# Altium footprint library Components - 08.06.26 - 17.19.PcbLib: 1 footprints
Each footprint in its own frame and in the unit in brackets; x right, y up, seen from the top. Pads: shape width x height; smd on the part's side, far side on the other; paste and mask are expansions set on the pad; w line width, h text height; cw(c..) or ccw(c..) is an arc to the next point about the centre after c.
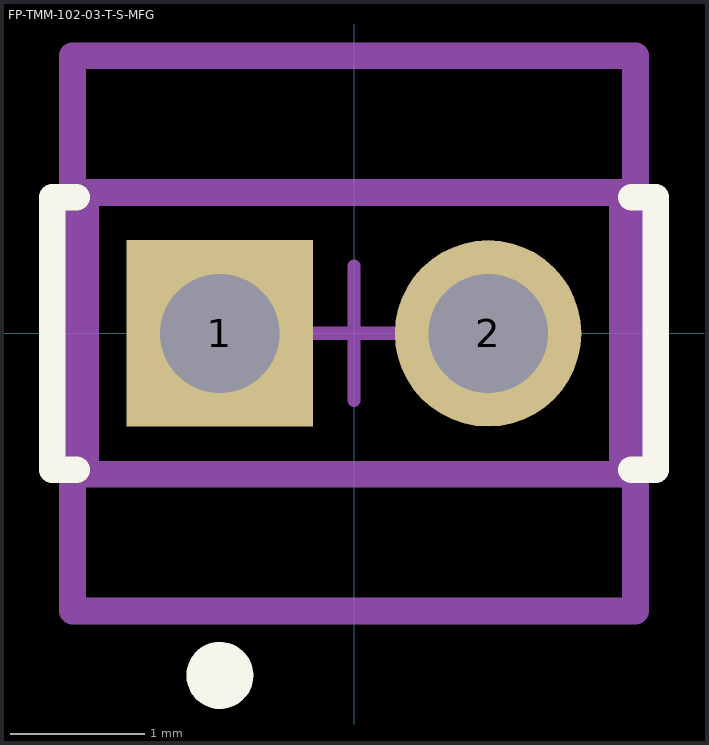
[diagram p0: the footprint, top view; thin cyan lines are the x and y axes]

## FP-TMM-102-03-T-S-MFG [mm]
pads (2):
  rect 1.39x1.39 hole 0.89 paste-2539.97 mask+0: 1(-1,0)
  round 1.39 hole 0.89 paste-2539.97 mask+0: 2(1,0)
Top Overlay:
  circle w0.25: c-1,-2.55 r0.125
  lines w0.2: -2.07,-1.016 -2.25,-1.016 -2.25,1.016 -2.07,1.016 ; 2.07,-1.016 2.25,-1.016 2.25,1.016 2.07,1.016
Top Paste:
  region: -0.15,-0.85 -1.85,-0.85 -1.85,0.85 -1.385,0.85 -1.36,0.852 -1.313,0.872 -1.277,0.908 -1.257,0.955 -1.255,0.98 -1.255,1.97 -0.745,1.97 -0.745,0.98 -0.743,0.955 -0.723,0.908 -0.687,0.872 -0.64,0.852 -0.615,0.85 -0.15,0.85
  region: 0.15,0.85 1.85,0.85 1.85,-0.85 1.385,-0.85 1.36,-0.852 1.313,-0.872 1.277,-0.908 1.257,-0.955 1.255,-0.98 1.255,-1.97 0.745,-1.97 0.745,-0.98 0.743,-0.955 0.723,-0.908 0.687,-0.872 0.64,-0.852 0.615,-0.85 0.15,-0.85
Top Assembly:
  lines w0.2: -2.1,-2.07 -2.1,2.07 2.1,2.07 2.1,-2.07 -2.1,-2.07
  text ".Designator" at 0,0.188 h1
Top 3D Body:
  lines w0.2: -2,-1.05 -2,1.05 2,1.05 2,-1.05 -2,-1.05
Top Courtyard:
  lines w0.2: -2.1,-2.07 -2.1,2.07 2.1,2.07 2.1,-2.07 -2.1,-2.07
Top Component Center:
  lines w0.1: -0.5,0 0.5,0 ; 0,-0.5 0,0.5
3D body "Conn_Samtec_TMM-102-03-T-S_eec.STEP": height 0.25, standoff 0, extent -2.1,-2.07 2.1,2.07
